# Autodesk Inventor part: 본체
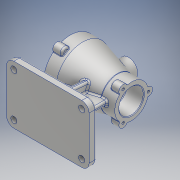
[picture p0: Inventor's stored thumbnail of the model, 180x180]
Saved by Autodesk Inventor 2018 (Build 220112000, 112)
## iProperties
Created: 2020-03
Part Number: 본체
Material: 알루미늄 6061
Document SubType Name: Modeling
Designer: Administrator
Density: 2.7 g/cm^3
Appearance: 알루미늄 - 평지
Author: Administrator
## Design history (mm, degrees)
sketch "스케치1"
  geometry: L1 (67.5, -47.5)-(-67.5, -47.5); L2 (-67.5, -47.5)-(-67.5, 47.5); L3 (-67.5, 47.5)-(67.5, 47.5); L4 (67.5, 47.5)-(67.5, -47.5); L5 (67.5, -47.5)-(-67.5, 47.5); L6 (-67.5, -47.5)-(67.5, 47.5); 1 further point
  constraints: 12 end point, 2 midpoint, 2 parallel, 1 horizontal, 1 perpendicular
  dimensions: "d0" = 135 distance of L1.start L1.end; "d1" = 95 distance of L1.end L2.end
extrude "돌출1" new body sketch "스케치1" distance "d2" = 12; taper "d3" = 0 deg
fillet "모깎기1" dims "d4" = 12
sketch "스케치2"
  geometry: A1 r 12 centre (-55.5, 35.5) between (-55.5, 47.5) and (-67.5, 35.5) reference; A2 r 12 centre (-55.5, -35.5) between (-67.5, -35.5) and (-55.5, -47.5) reference; A3 r 12 centre (55.5, -35.5) between (55.5, -47.5) and (67.5, -35.5) reference; A4 r 12 centre (55.5, 35.5) between (67.5, 35.5) and (55.5, 47.5) reference; 5 further points
  constraints: 4 coincident
hole "구멍1" sketch "스케치2" at (-55.5, 35.5), (-55.5, -35.5), (55.5, -35.5), (55.5, 35.5) diameter "d5" = 10; stored, may be unused: countersink angle "d9" = 90 deg, drill point angle "d11" = 118 deg; dims "d6" = 6, "d7" = 4, "d8" = 2, "d10" = 8
sketch "스케치3"
  geometry: L1 (0, 0)-(0, 87); L2 (-50, 87)-(50, 87); L3 (-50, 87)-(-50, 105.183); L4 (-50, 105.183)-(-50, 131); L5 (-50, 131)-(-30, 131); L6 (-30, 131)-(27, 114.5); L7 (27, 114.5)-(50, 114.5); L8 (50, 114.5)-(50, 87)
  constraints: 16 end point, 2 perpendicular, 1 horizontal, 1 midpoint, 1 parallel, 1 point on line, 1 vertical
  dimensions: "d12" = 87 distance of L1.end L1.start; "d13" = 100 distance of L2.start L2.end; "d14" = 88 diameter of L5 L2; "d15" = 55 diameter of L7 L2; "d16" = 20 distance from line of L5.end L4; "d17" = 77 distance from line of L6.end L4
revolve "회전1" sketch "스케치3" stored, may be unused: angle "d18" = 90 deg
sketch "스케치4"
  geometry: C1 r 7 at (0, 44); 2 further points
  constraints: 1 centre point, 1 vertical alignment, 1 other
  dimensions: "d19" = 14 diameter of C1
extrude "돌출2" join sketch "스케치4" distance "d20" = 15; taper "d21" = 0 deg
fillet "모깎기2" dims "d22" = 3
fillet "모깎기3" dims "d23" = 1
sketch "스케치5"
  geometry: A1 r 7 centre (0, 0) between (6.996, 0.249) and (-6.996, 0.249) reference; A2 r 7 centre (-38.105, -66) between (-41.818, -60.066) and (-34.823, -72.183) reference; A3 r 7 centre (38.105, -66) between (34.823, -72.183) and (41.818, -60.066) reference; 4 further points
  constraints: 3 coincident
hole "구멍2" sketch "스케치5" at (0, 0), (-38.105, -66), (38.105, -66) diameter "d27" = 4.134; stored, may be unused: countersink angle "d31" = 90 deg, drill point angle "d33" = 118 deg; dims "d28" = 9, "d29" = 4, "d30" = 2, "d32" = 11
sketch "스케치6"
  geometry: C1 r 27.5 at (0, 0) reference; C2 r 7 at (0, 27.5); 2 further points
  constraints: 1 centre point, 1 vertical alignment, 1 other
  dimensions: "d34" = 14 diameter of C2
extrude "돌출3" join sketch "스케치6" distance "d35" = 15; taper "d36" = 0 deg
fillet "모깎기4" dims "d37" = 3
fillet "모깎기5" dims "d38" = 1
sketch "스케치7"
  geometry: A1 r 4 centre (0, 0) between (3.933, 0.727) and (-3.933, 0.727) reference; A2 r 7 centre (-23.816, -41.25) between (-27.205, -35.125) and (-20.206, -47.248) reference; A3 r 7 centre (23.816, -41.25) between (20.206, -47.248) and (27.205, -35.125) reference; 4 further points
  constraints: 3 coincident
hole "구멍3" sketch "스케치7" at (0, 0), (-23.816, -41.25), (23.816, -41.25) diameter "d42" = 4.134; stored, may be unused: countersink angle "d46" = 90 deg, drill point angle "d48" = 118 deg; dims "d43" = 9, "d44" = 4, "d45" = 2, "d47" = 11
node "작업 평면1"
sketch "스케치8"
  geometry: C1 r 15 at (0, 0); 1 further point
  constraints: 1 centre point, 1 coincident
  dimensions: "d50" = 30 diameter of C1
extrude "돌출4" join sketch "스케치8" stored distance "d51" = 15; taper "d52" = 0 deg
sketch "스케치9"
  geometry: L1 (0, 0)-(0, 87); L2 (-50, 87)-(50, 87); L3 (-50, 87)-(-27, 87); L4 (-27, 87)-(-27, 123); L5 (-27, 123)-(-50, 123); L6 (-50, 123)-(-50, 87); L7 (-27, 87)-(20, 87); L8 (20, 87)-(20, 113); L9 (20, 113)-(-27, 113); L10 (-27, 113)-(-27, 87); L11 (50, 80.487)-(50, 113.395) reference; L12 (20, 87)-(50, 87); L13 (50, 87)-(50, 107); L14 (50, 107)-(20, 107); L15 (20, 107)-(20, 87)
  constraints: 28 end point, 6 parallel, 4 horizontal, 3 perpendicular, 1 midpoint, 1 point on line, 1 vertical
  dimensions: "d53" = 87 distance of L1.end L1.start; "d54" = 100 distance of L2.start L2.end; "d55" = 23 distance of L4.end L5.end; "d56" = 47 distance of L8.end L9.end; "d58" = 72 diameter of L5 L2; "d59" = 40 diameter of L14 L2; "d60" = 52 diameter of L9 L2
revolve "회전2" sketch "스케치9" stored, may be unused: angle "d61" = 90 deg
fillet "모깎기6" dims "d62" = 1
sketch "스케치10"
  geometry: C1 r 10 at (0, 0); 1 further point
  constraints: 1 centre point, 1 coincident
  dimensions: "d63" = 20 diameter of C1
extrude "돌출5" cut sketch "스케치10" stored distance "d64" = 15; taper "d65" = 0 deg; dims "d99" = 1
chamfer "모따기1" distance "d66" = 1; stored, may be unused: second distance "d67" = 2, angle "d68" = 45 deg
sketch "스케치12"
  geometry: L1 (12, 35.5)-(12, -35.5) reference; L2 (70.27, 19.902)-(12, 25); L3 (70.27, -19.902)-(12, -25); C1 r 26 at (87, 0) reference; A1 r 26 centre (87, 0) between (70.27, 19.902) and (70.27, -19.902); 2 further points
  constraints: 4 end point, 2 point on circle, 2 point on line, 1 centre point, 1 coincident
  dimensions: "d79" = 25 vertical distance of point (0, 0) L2.end; "d80" = 25 vertical distance of point (0, 0) L3.end; "d81" = 95 deg angle of L1 L3; "d82" = 95 deg angle of L1 L2
extrude "돌출6" join sketch "스케치12" distance "d83" = 8; taper "d84" = 0 deg
fillet "모깎기7" dims "d85" = 3
sketch "스케치13"
  geometry: L1 (-37, 46.144)-(-37, 8.115); L2 (37, 61.876)-(37, 8.115); L3 (55.5, 12)-(-55.5, 12) reference; L4 (-37, 8.115)-(-26.771, 8.115); L5 (-26.771, 8.115)-(37, 8.115); L6 (-25.641, 50.307)-(15.958, 58.823); L7 (15.958, 58.823)-(32.438, 63.131); L8 (32.438, 63.131)-(37, 63.131); L9 (37, 63.131)-(37, 61.876); A1 r 17.577 centre (-37, 63.72) between (-37, 46.144) and (-25.641, 50.307); 1 further point
  constraints: 16 end point, 2 perpendicular, 2 point on circle, 2 point on line, 1 centre point, 1 collinear, 1 horizontal, 1 vertical
  dimensions: "d86" = 37 distance from line of L2 point (0, 0); "d87" = 37 distance from line of point (0, 0) L1
extrude "돌출7" join sketch "스케치13" distance "d88" = 8; taper "d89" = 0 deg
fillet "모깎기8" dims "d90" = 3
fillet "모깎기9" dims "d91" = 3
fillet "모깎기10" dims "d92" = 3
fillet "모깎기11" dims "d93" = 3
fillet "모깎기12" dims "d94" = 3
fillet "모깎기13" dims "d95" = 3
fillet "모깎기14" dims "d96" = 3
fillet "모깎기15" dims "d97" = 3
fillet "모깎기16" dims "d98" = 3
chamfer "모따기2" distance "d99" = 1; stored, may be unused: second distance "d100" = 2, angle "d101" = 45 deg
chamfer "모따기3" distance "d102" = 1; stored, may be unused: second distance "d103" = 2, angle "d104" = 45 deg
fillet "모깎기17" dims "d105" = 3
fillet "모깎기18" dims "d106" = 3
fillet "모깎기19" dims "d107" = 3
fillet "모깎기20" dims "d108" = 3
sketch "스케치14"
  geometry: L1 (-55.5, -47.5)-(55.5, -47.5) reference; 2 further points
  constraints: 1 vertical alignment, 1 other
  dimensions: "d109" = 10 distance from line of L1 point (0, -37.5)
feature "엠보싱1" sketch "스케치14" dims "d110" = 0.5, "d111" = 0
node "솔리드1"
pattern_circular "원형 패턴1" dims angle "d25" = 360 deg
pattern_circular "원형 패턴2" dims angle "d40" = 360 deg
node "투영된 루프1"
other parameters: "d49" = 132
